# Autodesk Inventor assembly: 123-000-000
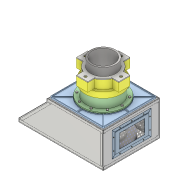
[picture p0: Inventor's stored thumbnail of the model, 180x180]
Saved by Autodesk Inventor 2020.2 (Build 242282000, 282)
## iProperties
Created: 2006-08
Part Number: 123-000-000
Document SubType Name: Assembly
Designer: F.Stasiak
Description: Zespół głowicy obrotowej
Mass: 1.20329e+06 g
Surface Area: 220449 cm^2
Volume: 203819 cm^3
Density: 5.90373 g/cm^3
Company: Fabian Stasiak CAD Consulting
Manager: www.cadconsulting.pl
Author: F.Stasiak
Subject: Zbiór ćwiczeń. Autodesk Inventor 2020. Kurs podstawowy
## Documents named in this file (12)
- C:\2020_Kurs_podstawowy\R6 Zespoły\BOM\123-000-000.iam
- C:\2020_Kurs_podstawowy\R6 Zespoły\BOM\123-456-000.iam
- C:\2020_Kurs_podstawowy\R6 Zespoły\BOM\123-400-003.ipt
- C:\2020_Kurs_podstawowy\R6 Zespoły\BOM\123-400-007.ipt
- C:\2020_Kurs_podstawowy\R6 Zespoły\BOM\123-400-015.ipt
- C:\2020_Kurs_podstawowy\R6 Zespoły\BOM\123-350-000.iam
- C:\2020_Kurs_podstawowy\R6 Zespoły\BOM\123-000-000\Design Accelerator\Połączenie gwintowe1.iam
- C:\2020_Kurs_podstawowy\R6 Zespoły\BOM\123-000-000\Design Accelerator\Połączenie gwintowe2.iam
- C:\2020_Kurs_podstawowy\R6 Zespoły\BOM\123-500-000.iam
- C:\2020_Kurs_podstawowy\R6 Zespoły\BOM\123-400-016.ipt
- C:\2020_Kurs_podstawowy\R6 Zespoły\BOM\123-400-017.ipt
- C:\2020_Kurs_podstawowy\R6 Zespoły\BOM\123-000-000\Design Accelerator\Połączenie gwintowe3.iam
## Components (34 placed, 9 different names)
1. 123-456-000:1 [sub-assembly] — Zestawiający:1, Zestawiający:2, Równoległy:1, Wstaw:1, Wstaw:2, Wstaw:3, Wstaw:4, Równoległe:2
2. 123-350-000:1 [sub-assembly] — Wstaw:1, Wstaw:2, Wstaw:5, Wstaw:6, Kąt:1, Zestawiający:3, Zestawiający:4, Zestawiające:7
3. 123-400-003:1 — Wstaw:3, Wstaw:4
4. 123-400-007:1 — Wstaw:5, Wstaw:6, Zestawiający:5, Zestawiający:6
5. 123-400-015:1 — Zestawiający:1, Zestawiający:2, Równoległy:1, Kąt:1, Zestawiające:8, Zestawiające:9, Zestawiające:10, Zestawiające:11
6. 123-500-000:1 [sub-assembly] — Zestawiające:7, Równoległe:2
7. 123-400-016:1 — Zestawiające:8, Zestawiające:9, Zestawiające:10, Zestawiające:11, Równoległe:3, Zestawiające:12, Zestawiające:13
8. 123-400-017:1 — Równoległe:3
9. Połączenie gwintowe:1 [sub-assembly] — Zestawiający:3, Zestawiający:4
10. Połączenie gwintowe:2 [sub-assembly]
11. Połączenie gwintowe:3 [sub-assembly]
12. Połączenie gwintowe:4 [sub-assembly]
13. Połączenie gwintowe:5 [sub-assembly]
14. Połączenie gwintowe:6 [sub-assembly]
15. Połączenie gwintowe:7 [sub-assembly]
16. Połączenie gwintowe:8 [sub-assembly]
17. Połączenie gwintowe:9 [sub-assembly]
18. Połączenie gwintowe:10 [sub-assembly]
19. Połączenie gwintowe:11 [sub-assembly] — Zestawiający:5, Zestawiający:6
20. Połączenie gwintowe:12 [sub-assembly]
21. Połączenie gwintowe:13 [sub-assembly]
22. Połączenie gwintowe:14 [sub-assembly]
23. Połączenie gwintowe:15 [sub-assembly]
24. Połączenie gwintowe:16 [sub-assembly]
25. Połączenie gwintowe:17 [sub-assembly] — Zestawiające:12, Zestawiające:13
26. Połączenie gwintowe:18 [sub-assembly]
27. Połączenie gwintowe:19 [sub-assembly]
28. Połączenie gwintowe:20 [sub-assembly]
29. Połączenie gwintowe:21 [sub-assembly]
30. Połączenie gwintowe:22 [sub-assembly]
31. Połączenie gwintowe:23 [sub-assembly]
32. Połączenie gwintowe:24 [sub-assembly]
33. Połączenie gwintowe:25 [sub-assembly]
34. Połączenie gwintowe:26 [sub-assembly]
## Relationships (23: Mate 13, Insert 6, Flush 3, Angle 1)
- Zestawiający:1 [Mate]: 123-456-000:1 ↔ 123-400-015:1
- Zestawiający:2 [Mate]: 123-456-000:1 ↔ 123-400-015:1
- Równoległy:1 [Flush]: 123-456-000:1 ↔ 123-400-015:1
- Wstaw:1 [Insert]: 123-456-000:1 ↔ 123-350-000:1
- Wstaw:2 [Insert]: 123-456-000:1 ↔ 123-350-000:1
- Wstaw:3 [Insert]: 123-456-000:1 ↔ 123-400-003:1
- Wstaw:4 [Insert]: 123-456-000:1 ↔ 123-400-003:1
- Wstaw:5 [Insert]: 123-350-000:1 ↔ 123-400-007:1
- Wstaw:6 [Insert]: 123-350-000:1 ↔ 123-400-007:1
- Kąt:1 [Angle]: 123-350-000:1 ↔ 123-400-015:1
- Zestawiający:3 [Mate]: 123-350-000:1 ↔ Połączenie gwintowe:1
- Zestawiający:4 [Mate]: 123-350-000:1 ↔ Połączenie gwintowe:1
- Zestawiający:5 [Mate]: 123-400-007:1 ↔ Połączenie gwintowe:11
- Zestawiający:6 [Mate]: 123-400-007:1 ↔ Połączenie gwintowe:11
- Zestawiające:7 [Mate]: 123-350-000:1 ↔ 123-500-000:1
- Równoległe:2 [Flush]: 123-456-000:1 ↔ 123-500-000:1
- Zestawiające:8 [Mate]: 123-400-015:1 ↔ 123-400-016:1
- Zestawiające:9 [Mate]: 123-400-015:1 ↔ 123-400-016:1
- Zestawiające:10 [Mate]: 123-400-015:1 ↔ 123-400-016:1
- Zestawiające:11 [Mate]: 123-400-015:1 ↔ 123-400-016:1
- Równoległe:3 [Flush]: 123-400-016:1 ↔ 123-400-017:1
- Zestawiające:12 [Mate]: 123-400-016:1 ↔ Połączenie gwintowe:17
- Zestawiające:13 [Mate]: 123-400-016:1 ↔ Połączenie gwintowe:17
